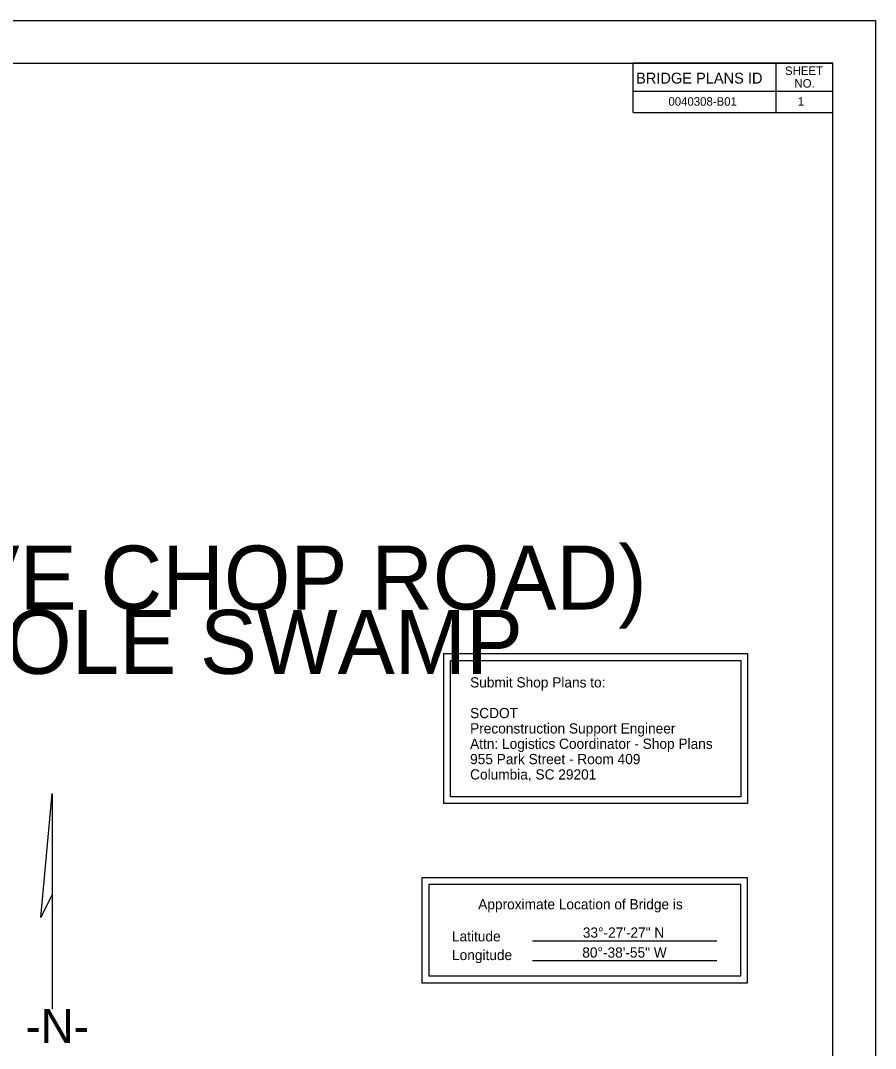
# Model space of a CAD drawing. Extents: x 140 to 1940, y 64 to 1307.
# Drawn here: x 1438 to 1940, y 561 to 1164 of the extents above; entities that cross this region are included whole.
import ezdxf

# ---------------------------------------------------------------- set-up
doc = ezdxf.new("R2010")
doc.units = 0
for name, color, linetype in [('BR_BORDER LINES', 7, 'Continuous'), ('BR_DETAILS', 7, 'Continuous'), ('BR_TEXT', 7, 'Continuous'), ('Default', 7, 'Continuous'), ('RD_SHT_IplotShp', 7, 'Continuous')]:
    doc.layers.add(name, color=color, linetype=linetype)

msp = doc.modelspace()

# ---------------------------------------------------------------- linework, layer by layer
at = {"layer": 'BR_BORDER LINES'}
for p, q in [((239.58, 1138.98), (1914.58, 1138.98)), ((1914.58, 88.98), (1914.58, 1138.98)), ((1914.58, 1080.7), (1914.58, 1105.57)), ((1914.58, 728.24), (1914.58, 1080.7))]:
    msp.add_line(p, q, dxfattribs=at)
at = {"layer": 'BR_DETAILS'}
for p, q in [((1797.51, 1110.04), (1797.51, 1138.98)), ((1914.58, 1138.98), (1797.51, 1138.98)), ((1881.08, 1138.98), (1881.08, 1110.04)), ((1914.58, 1110.04), (1914.58, 1138.98)), ((1797.51, 1122.54), (1914.58, 1122.54)), ((1831.01, 1122.54), (1914.58, 1122.54)), ((1797.51, 1110.04), (1914.58, 1110.04)), ((1831.01, 1110.04), (1914.58, 1110.04)), ((1738.48, 624.13), (1846.62, 624.13)), ((1738.48, 612.54), (1846.62, 612.54))]:
    msp.add_line(p, q, dxfattribs=at)
for points in [[(1686.37, 792.61), (1864.58, 792.61), (1864.58, 704.58), (1686.37, 704.58)], [(1690.37, 788.61), (1860.58, 788.61), (1860.58, 708.58), (1690.37, 708.58)], [(1864.62, 661.13), (1673.56, 661.13), (1673.56, 599.54), (1864.62, 599.54)], [(1860.62, 657.13), (1677.56, 657.13), (1677.56, 603.54), (1860.62, 603.54)]]:
    msp.add_lwpolyline(points, close=True, dxfattribs=at)
at = {"layer": 'Default'}
for p, q in [((1450.02, 637.77), (1456.68, 710.56)), ((1456.68, 710.56), (1456.68, 651.28)), ((1456.68, 651.28), (1450.02, 637.77)), ((1456.68, 651.28), (1456.68, 610.19)), ((1456.68, 610.19), (1456.68, 583.99))]:
    msp.add_line(p, q, dxfattribs=at)
at = {"layer": 'RD_SHT_IplotShp'}
msp.add_lwpolyline([(139.58, 1163.91), (1939.58, 1163.91), (1939.58, 63.91), (139.58, 63.91)], close=True, dxfattribs=at)

# ---------------------------------------------------------------- texts
at = {"layer": 'BR_DETAILS'}
for s, height, p in [('SHEET', 5, (1886.54, 1131.98)), ('BRIDGE PLANS ID', 6.3953, (1799.2, 1126.94)), ('NO.', 5, (1892.08, 1124.55)), ('US ROUTE 301 SOUTHBOUND (FIVE CHOP ROAD)', 37.5, (601.75, 818.43)), ('REPLACE BRIDGE OVER FOUR HOLE SWAMP', 37.5, (626.64, 780.71)), ('Submit Shop Plans to:', 6, (1701.84, 772.71)), ('SCDOT', 6, (1701.84, 754.71)), ('Preconstruction Support Engineer', 6, (1701.84, 745.71)), ('Attn: Logistics Coordinator - Shop Plans', 6, (1701.84, 736.71)), ('955 Park Street - Room 409', 6, (1701.84, 727.71)), ('Columbia, SC 29201', 6, (1701.84, 718.71)), ('Approximate Location of Bridge is', 6, (1706.61, 642.57)), ('Latitude', 6, (1691.2, 623.76)), ('Longitude', 6, (1691.25, 612.8))]:
    msp.add_text(s, height=height, dxfattribs=at).set_placement(p)
at = {"layer": 'BR_TEXT'}
for s, height, p in [('0040308-B01', 5, (1818.16, 1113.95)), ('1', 5, (1894.03, 1113.95)), ('33%%d-27\'-27" N', 6, (1767.97, 625.93)), ('80%%d-38\'-55" W', 6, (1767.65, 614.28))]:
    msp.add_text(s, height=height, dxfattribs=at).set_placement(p)
at = {"layer": 'Default'}
msp.add_text('-N-', height=20, dxfattribs=at).set_placement((1441.11, 564.12))

doc.saveas('drawing.dxf')
